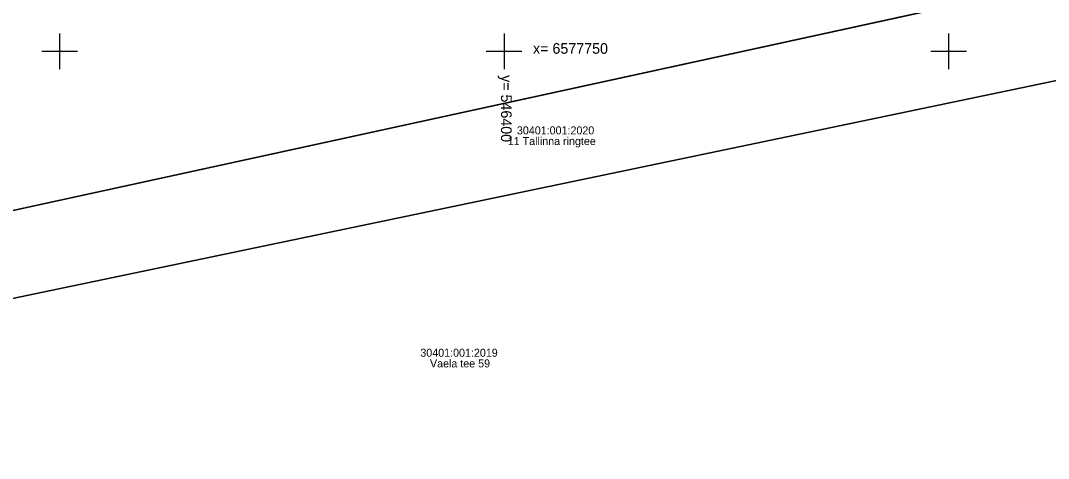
# Model space of a CAD drawing. Extents: x 543497 to 552146, y 6567125 to 6579845.
# Drawn here: x 546345.6 to 546461.2, y 6577704.2 to 6577753.5 of the extents above; entities that cross this region are included whole.
import ezdxf

# ---------------------------------------------------------------- set-up
doc = ezdxf.new("R2010")
doc.units = 0
doc.layers.add('xref_Kangru tee 1_geodeesia$0$PIIR', color=7, linetype='Continuous')
doc.layers.add('xref_Kangru tee 1_geodeesia$0$vork', color=7, linetype='Continuous')

# ---------------------------------------------------------------- blocks, each defined once
blk = doc.blocks.new('xref_Kangru tee 1_geodeesia$0$VKORIS')
for p, q in [((0, 4), (0, -4)), ((-4, 0), (4, 0))]:
    blk.add_line(p, q)

msp = doc.modelspace()

# ---------------------------------------------------------------- linework, layer by layer
at = {"layer": 'xref_Kangru tee 1_geodeesia$0$PIIR'}
for points in [[(546508.03, 6577841.48), (546527.76, 6577842.6), (546535.64, 6577829.79), (546540.71, 6577817.81), (546551.12, 6577809.99), (546561.59, 6577802.16), (546622.52, 6577814.88), (546633.51, 6577792.62), (546608.95, 6577787.91), (546573.78, 6577780.87), (546521.59, 6577770.69), (546316.12, 6577725.86), (546173.38, 6577691.06), (546034.23, 6577654.21), (545899.95, 6577611.29), (545780.54, 6577566.57), (545623.97, 6577499.02), (545555.77, 6577467.67), (545385.83, 6577376.92), (545249.19, 6577295.85), (545250.22, 6577289.9), (544980.83, 6577118.49)], [(546317.36, 6577716.48), (546316.18, 6577725.87), (546521.59, 6577770.69), (546544.17, 6577758.03), (546562.86, 6577702.03), (546555.07, 6577698.83), (546526.41, 6577760.19), (546317.36, 6577716.48)], [(546327.18, 6577637.77), (546317.36, 6577716.48), (546526.41, 6577760.19), (546555.07, 6577698.83), (546488.12, 6577671.33), (546448.33, 6577655.12), (546438.58, 6577671.53), (546327.18, 6577637.77)]]:
    msp.add_lwpolyline(points, dxfattribs=at)

# ---------------------------------------------------------------- block references
at = {"layer": 'xref_Kangru tee 1_geodeesia$0$vork', "xscale": 0.5, "yscale": 0.5}
for p in [(546350, 6577750), (546400, 6577750), (546450, 6577750)]:
    msp.add_blockref('xref_Kangru tee 1_geodeesia$0$VKORIS', p, dxfattribs=at)

# ---------------------------------------------------------------- texts
at = {"layer": 'xref_Kangru tee 1_geodeesia$0$PIIR'}
for s, p in [('30401:001:2020', (546401.44, 6577740.65)), ('11 Tallinna ringtee', (546400.41, 6577739.45)), ('30401:001:2019', (546390.58, 6577715.63)), ('Vaela tee 59', (546391.66, 6577714.43))]:
    msp.add_text(s, height=0.9, dxfattribs=at).set_placement(p)
at = {"layer": 'xref_Kangru tee 1_geodeesia$0$vork'}
msp.add_text('x= 6577750', height=1.2, dxfattribs=at).set_placement((546403.25, 6577749.72))
msp.add_text('y= 546400', height=1.2, rotation=270, dxfattribs=at).set_placement((546399.65, 6577747.32))

doc.saveas('drawing.dxf')
